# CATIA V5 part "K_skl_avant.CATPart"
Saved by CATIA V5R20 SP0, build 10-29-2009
Part number: skl_avant
Publications: "Axe_avant_guidon", "Plan_avant_guidon"
Bounding box of the stored display mesh (mm): x -20 to 20, y -20 to 20, z 0 to 0
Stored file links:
  G:\Khaled_CFAO_2011\SIL\SIL_GR2\ahabrial\ahabrial\Khaled\CAD_ThinkMOTION\K_skl_avant.CATPart
  G:\Données\Ecole\IFMA\2A\Thinkmotion2\Etape18\trotinette.CATProduct
  G:\Khaled_CFAO_2011\SIL\SIL_GR2\ahabrial\ahabrial\Khaled\CAD_ThinkMOTION\K_skl_arriere.CATPart
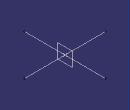
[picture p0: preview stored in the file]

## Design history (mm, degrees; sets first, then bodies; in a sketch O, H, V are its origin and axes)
Set1
  Point1: linked copy from another document
  Line1 "Droite_arriere": linked copy from another document
  Plane1 "Plan_ref": linked copy from another document
Body1 (main body)
  Line2 "Droite_avant": type PtDir, RefPoint Point1, Direction (0, 1, 0), Start -20, End 20
  Line3 "Axe_avant_guidon": type Normal, RefPoint Point1, RefSkin Plane1, Start -20, End 20
  Plane2 "Plan_avant_guidon": type 2Lines, Element1 Line2, Element2 Line3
